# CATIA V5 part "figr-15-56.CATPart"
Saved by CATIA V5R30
Part number: Part1
Bounding box of the stored display mesh (mm): x -75 to -29.087, y -20 to 20, z 0 to 62.461
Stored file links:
  D:\PROJECTS\CATIA V56R 2020\Resources\Parts File\c15_catia_v5_6r2020_prt\figr-15-56.CATPart
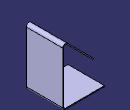
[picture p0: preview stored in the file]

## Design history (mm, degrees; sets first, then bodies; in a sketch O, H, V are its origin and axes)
SheetMetalParameters1: Thickness 1, BendRadius 2, KFactor 0.400515 {= log(min(100,max(20*SheetMetalParameters1.BendRadius,SheetMetalParameters1.Thickness)/SheetMetalParameters1.Thickness))/log(100)/2}, ReliefRadialLength 1, ReliefAxialLength 2, MinimumBendRadius 0
Body1 (main body)
  Sketch1 on xy-plane, origin (0, 0, 0), H (1, 0, 0), V (0, 1, 0)
    line L1 (-75, 20) -> (75, 20)
    line L2 (75, 20) -> (75, -20)
    line L3 (75, -20) -> (-75, -20)
    line L4 (-75, -20) -> (-75, 20)
    distance L1 L3 = 40
    distance L2 L4 = 150
    distance V L2 = 75
    distance H L3 = 20
    horizontal: L1 H, L3 H
    vertical: L2 V, L4 V
  Wall1: Thickness 1, Profile Sketch1
  Sketch2 on face of Wall1, origin (0, 0, 1), H (1, 0, 0), V (0, 1, 0)
    line L1 (-30.2021, 19.5432) -> (-30.2021, -20.6466)
    line L2 (31.0296, 19.5432) -> (31.0296, -20.6466)
    vertical: L1 V, L2 V
  FlatBend1: FlatBendAngle 90, FlatBendAngle 45, Axis Sketch2, FixedPoint vertex [face of Wall1 | face of Wall1 | face of Wall1], FlatBendKFactor 0.400515 {= log(min(100,max(20*FlatBend1.FlatBendRadius,SheetMetalParameters1.Thickness)/SheetMetalParameters1.Thickness))/log(100)/2}, FlatBendKFactor 0.400515 {= log(min(100,max(20*FlatBend1.FlatBendRadius,SheetMetalParameters1.Thickness)/SheetMetalParameters1.Thickness))/log(100)/2}, FlatBendRadius 2 {= SheetMetalParameters1.BendRadius}, FlatBendRadius 2 {= SheetMetalParameters1.BendRadius}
